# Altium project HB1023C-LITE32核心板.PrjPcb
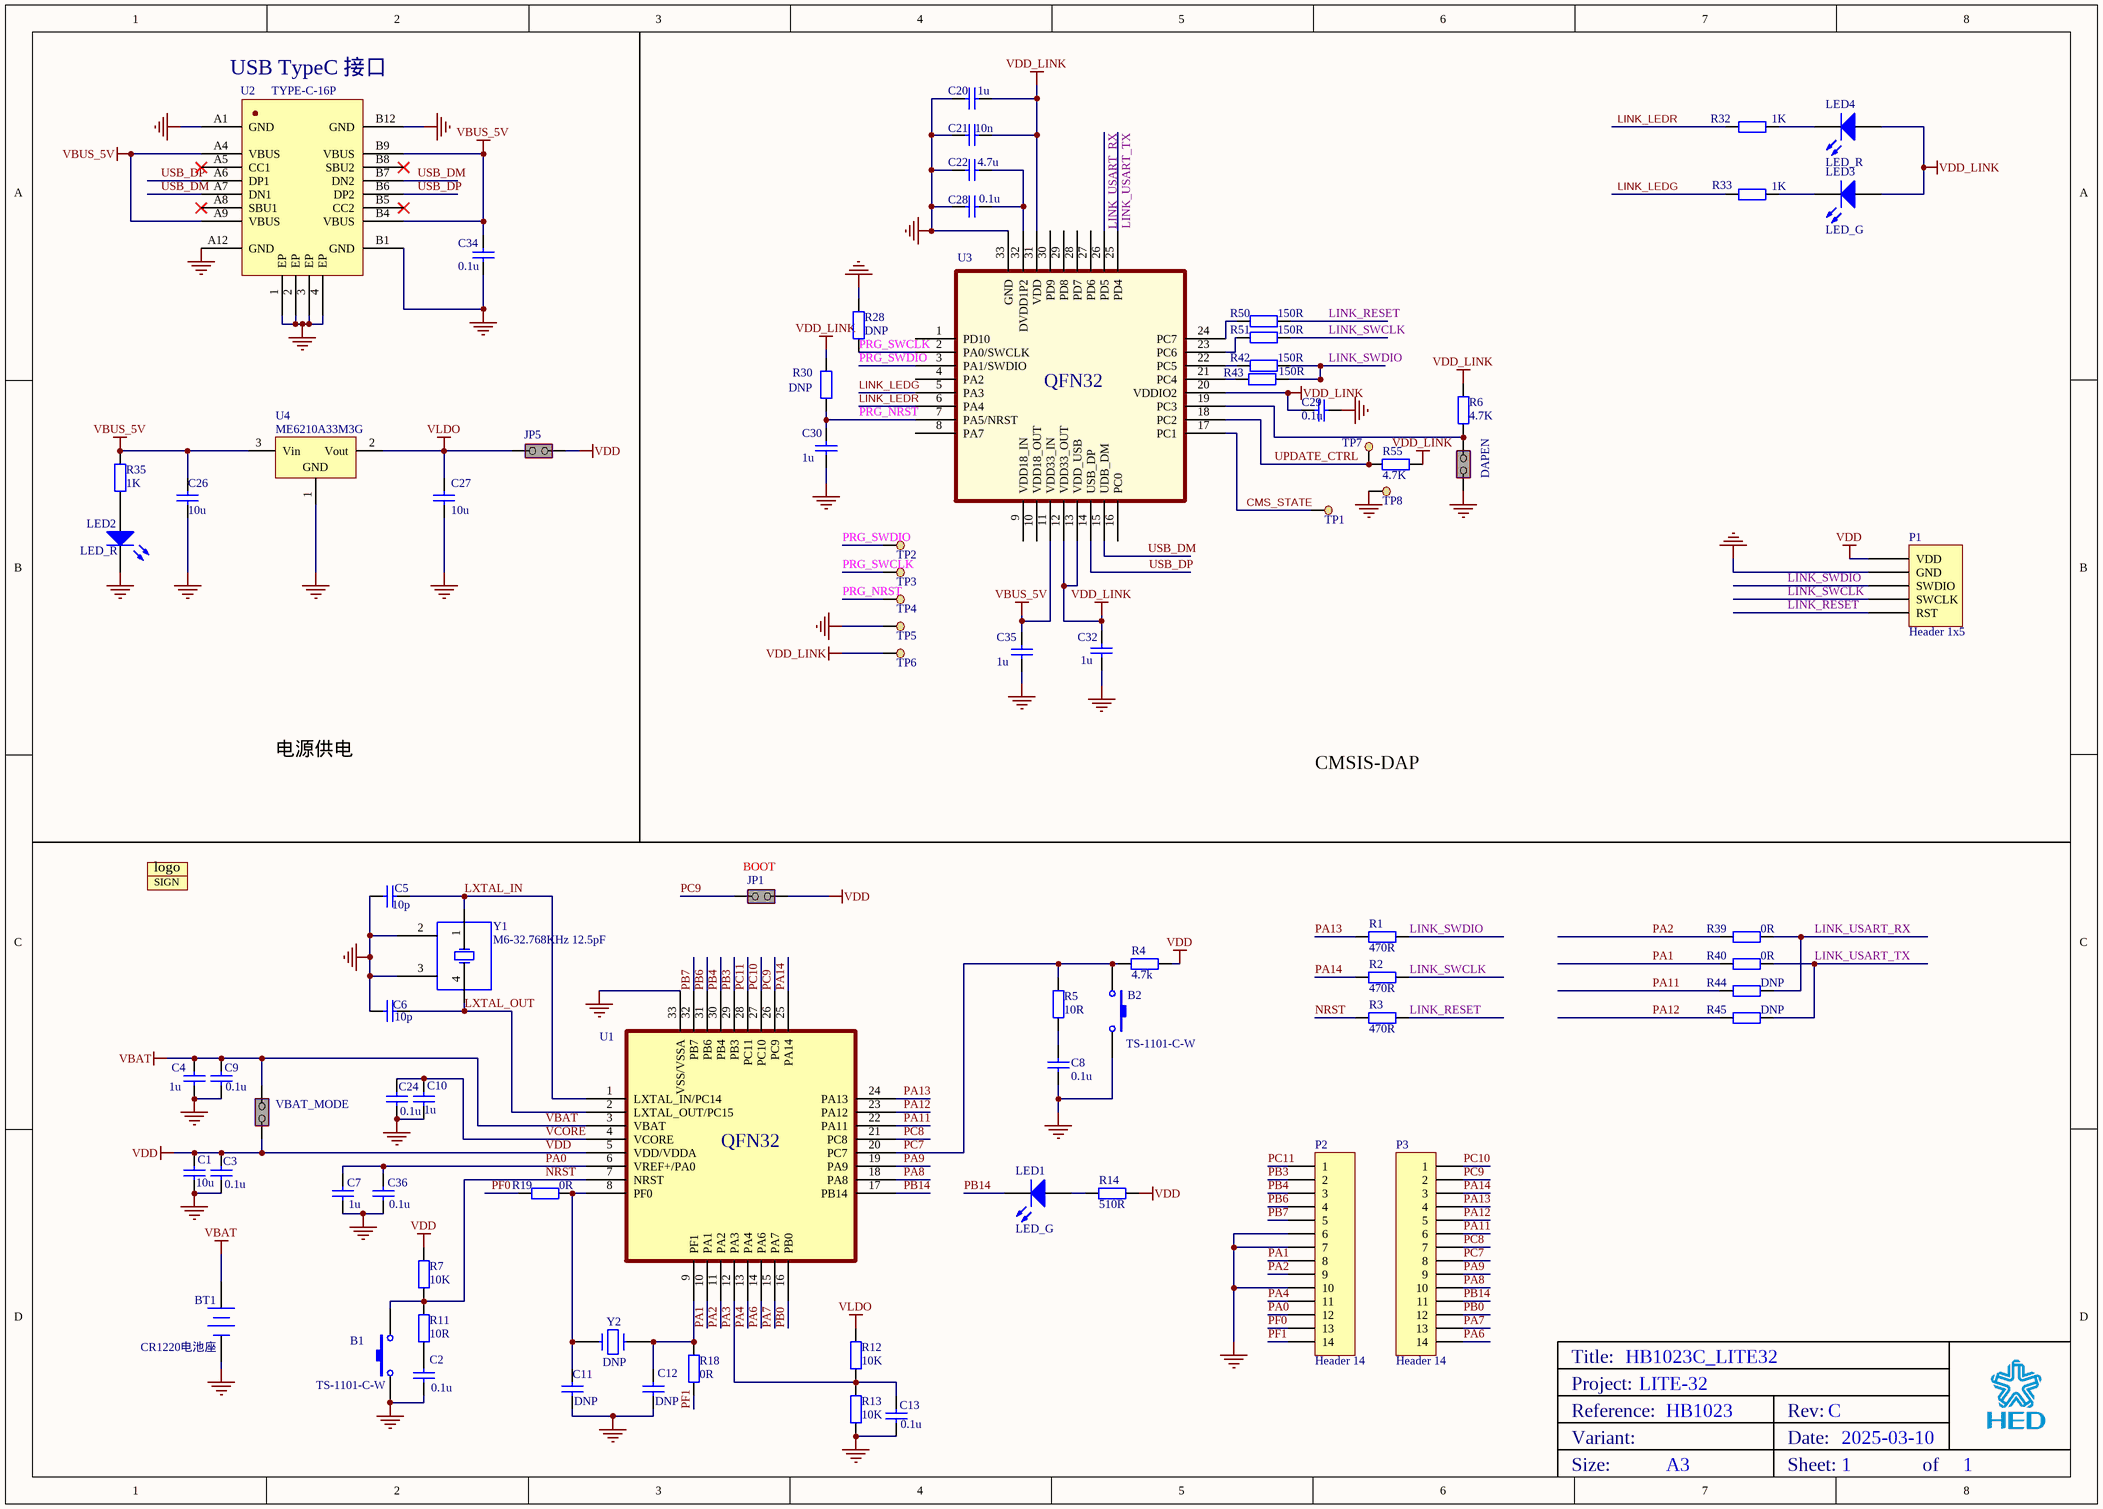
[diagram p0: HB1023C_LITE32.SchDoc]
Board_Reference: HB1023; Board_PCB_Revision: C; Board_Name: LITE-32; Board_Assembly_Revision: 01
1 sheet, 83 parts. Net scope: global (net labels, ports and power ports of the same name join across sheets).
Board file: HB1023C.PcbDoc

## Sheet HB1023C_LITE32.SchDoc: HB1023C_LITE32
size A3; Date: 2025-03-10; SheetNumber: 1; SheetTotal: 1

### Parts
B1  TS-1101-C-W  [按键_TS-1101-C-W]
B2  TS-1101-C-W  [按键_TS-1101-C-W]
BT1  CR1220电池座  [CR1220]
C1  10u  [0603]
C2  0.1u  [0603]
C3  0.1u  [0603]
C4  1u  [0603]
C5  10p  [0603]
C6  10p  [0603]
C7  1u  [0603]
C8  0.1u  [0603]
C9  0.1u  [0603]
C10  1u  [0603]
C11  DNP  [0603]
C12  DNP  [0603]
C13  0.1u  [0603]
C20  1u  [0603]
C21  10n  [0603]
C22  4.7u  [0603]
C24  0.1u  [0603]
C26  10u  [0603]
C27  10u  [0603]
C28  0.1u  [0603]
C29  0.1u  [0603]
C30  value 1u  [0603]  (hidden comment: 0.1u)
C32  1u  [0603]
C34  0.1u  [0603]
C35  1u  [0603]
C36  0.1u  [0603]
DAPEN  Header 1x2  [HEADER_1X2_2.54]  (value not drawn)
JP1  Header 1x2  [HEADER_1X2_2.54]  (value not drawn)
JP5  Header 1x2  [HEADER_1X2_2.54]  (value not drawn)
LED1  LED_G  [0603 - p]
LED2  LED_R  [0603-P]
LED3  LED_G  [0603-P]
LED4  LED_R  [0603-P]
logo1  logo  [LOGO]  (value not drawn)
logo2  SIGN  [SIGN]  (value not drawn)
P1  Header 1x5  [HDR1X5_2.54]
P2  Header 14  [HDR1X14]
P3  Header 14  [HDR1X14]
R1  470R  [0603]
R2  470R  [0603]
R3  470R  [0603]
R4  4.7k  [0603]
R5  10R  [0603]
R6  4.7K  [0603]
R7  10K  [0603]
R11  10R  [0603]
R12  10K  [0603]
R13  10K  [0603]
R14  510R  [0603]
R18  0R  [0603]
R19  0R  [0603]
R28  DNP  [0603]
R30  DNP  [0603]
R32  1K  [0603]
R33  1K  [0603]
R35  1K  [0603]
R39  0R  [0603]
R40  0R  [0603]
R42  150R  [0603]
R43  150R  [0603]
R44  DNP  [0603]
R45  DNP  [0603]
R50  150R  [0603]
R51  150R  [0603]
R55  4.7K  [0603]
TP1  TEST_POINT  [TEST_POINT]  (value not drawn)
TP2  TEST_POINT  [TEST_POINT]  (value not drawn)
TP3  TEST_POINT  [TEST_POINT]  (value not drawn)
TP4  TEST_POINT  [TEST_POINT]  (value not drawn)
TP5  TEST_POINT  [TEST_POINT]  (value not drawn)
TP6  TEST_POINT  [TEST_POINT]  (value not drawn)
TP7  TEST_POINT  [TEST_POINT]  (value not drawn)
TP8  TEST_POINT  [TEST_POINT]  (value not drawn)
U1  (no value)  [QFN_32N_4X4]
U2  TYPE-C-16P  [HED-KH-TYPE-C-16P]
U3  CIU98_H  [HED-QFN-32_5x5x05P]  (value not drawn)
U4  ME6210A33M3G  [SOT-23-3]
VBAT_MODE  Header 1x2  [HEADER_1X2_2.54]  (value not drawn)
Y1  M6-32.768KHz 12.5pF  [XTAL-MC146]
Y2  DNP  [XTAL_HC49/SMD]

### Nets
GND: B1.1 B2.1 BT1.2(-) C1.1 C2.2 C3.1 C4.1 C5.1 C6.1 C7.1 C8.1 C9.1 C10.2 C11.2 C12.2 C13.1 C20.1 C21.1 C22.1 C24.2 C26.1 C27.1 C28.1 C29.1 C30.2 C32.2 C34.1 C35.2 C36.1 DAPEN.2(NO) LED2.2(K) P1.2(GND) P2.6 P2.7 P2.10 R13.2 R28.1 TP5.1 TP8.1 U1.33(VSS/VSSA) U2.1(EP) U2.2(EP) U2.3(EP) U2.4(EP) U2.A1(GND) U2.A12(GND) U2.B1(GND) U2.B12(GND) U3.33(GND) U4.1(GND) Y1.2(OSC2) Y1.3(OSC4)
VBAT: BT1.1(+) C4.2 C9.2 U1.3(VBAT) VBAT_MODE.2(NO)
VBUS_5V: C26.2 C34.2 C35.1 R35.2 U2.A4(VBUS) U2.A9(VBUS) U2.B4(VBUS) U2.B9(VBUS) U3.11(VDD33_IN) U4.3(Vin)
VDD: C1.2 C3.2 JP1.2(NO) JP5.1(COMMON) P1.1(VDD) R4.2 R7.1 R14.2 U1.5(VDD/VDDA) VBAT_MODE.1(COMMON)
VDD_LINK: C20.2 C21.2 C29.2 C32.1 LED3.1(A) LED4.1(A) R6.2 R30.1 R55.1 TP6.1 U3.12(VDD33_OUT) U3.13(VDD_USB) U3.20(VDDIO2) U3.31(VDD)
VLDO: C27.2 JP5.2(NO) R12.2 U4.2(Vout)
CMS_STATE: TP1.1 U3.17(PC1)
LINK_LEDG: R33.1 U3.5(PA3)
LINK_LEDR: R32.1 U3.6(PA4)
LINK_RESET: P1.5(RST) R3.2 R50.2
LINK_SWCLK: P1.4(SWCLK) R2.2 R51.2
LINK_SWDIO: P1.3(SWDIO) R1.2 R42.2 R43.2
LINK_USART_RX: R39.1 R44.1 U3.26(PD5)
LINK_USART_TX: R40.1 R45.1 U3.25(PD4)
LXTAL_IN: C5.2 U1.1(LXTAL_IN/PC14) Y1.1(OSC1)
LXTAL_OUT: C6.2 U1.2(LXTAL_OUT/PC15) Y1.4(OSC3)
NRST: B1.2 R3.1 R7.2 R11.1 U1.7(NRST)
PA0: C7.2 C36.2 P2.12 U1.6(VREF+/PA0)
PA1: P2.8 R40.2 U1.10(PA1)
PA2: P2.9 R39.2 U1.11(PA2)
PA3: C13.2 R12.1 R13.1 U1.12(PA3)
PA4: P2.11 U1.13(PA4)
PA6: P3.14 U1.14(PA6)
PA7: P3.13 U1.15(PA7)
PA8: P3.10 U1.18(PA8)
PA9: P3.9 U1.19(PA9)
PA11: P3.6 R44.2 U1.22(PA11)
PA12: P3.5 R45.2 U1.23(PA12)
PA13: P3.4 R1.1 U1.24(PA13)
PA14: P3.3 R2.1 U1.25(PA14)
PB0: P3.12 U1.16(PB0)
PB3: P2.2 U1.29(PB3)
PB4: P2.3 U1.30(PB4)
PB6: P2.4 U1.31(PB6)
PB7: P2.5 U1.32(PB7)
PB14: LED1.2(K) P3.11 U1.17(PB14)
PC7: B2.2 P3.8 R4.1 R5.2 U1.20(PC7)
PC8: P3.7 U1.21(PC8)
PC9: JP1.1(COMMON) P3.2 U1.26(PC9)
PC10: P3.1 U1.27(PC10)
PC11: P2.1 U1.28(PC11)
PF0: P2.13 R19.2
PF1: P2.14 R18.2
PRG_NRST: C30.1 R30.2 TP4.1 U3.7(PA5/NRST)
PRG_SWCLK: R28.2 TP3.1 U3.2(PA0/SWCLK)
PRG_SWDIO: TP2.1 U3.3(PA1/SWDIO)
UPDATE_CTRL: R55.2 TP7.1 U3.18(PC2)
USB_DM: U2.A7(DN1) U2.B7(DN2) U3.15(UDB_DM)
USB_DP: U2.A6(DP1) U2.B6(DP2) U3.14(USB_DP)
VCORE: C10.1 C24.1 U1.4(VCORE)
NetC2_1: C2.1 R11.2
NetC8_2: C8.2 R5.1
NetC11_1: C11.1 R19.1 U1.8(PF0) Y2.1
NetC12_1: C12.1 R18.1 U1.9(PF1) Y2.2
NetC22_2: C22.2 C28.2 U3.32(DVDD1P2)
NetDAPEN_1: DAPEN.1(COMMON) R6.1 U3.19(PC3)
NetLED1_1: LED1.1(A) R14.1
NetLED2_1: LED2.1(A) R35.1
NetLED3_2: LED3.2(K) R33.2
NetLED4_2: LED4.2(K) R32.2
NetR42_1: R42.1 U3.22(PC5)
NetR43_1: R43.1 U3.21(PC4)
NetR50_1: R50.1 U3.24(PC7)
NetR51_1: R51.1 U3.23(PC6)

Not connected (* = marked no-connect by the designer): U2 A5(CC1)* A8(SBU1)* B5(CC2)* B8(SBU2)*; U3 1(PD10) 4(PA2) 8(PA7) 9(VDD18_IN) 10(VDD18_OUT) 16(PC0) 27(PD6) 28(PD7) 29(PD8) 30(PD9)

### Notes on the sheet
- (near U2) USB TypeC 接口
- 电源供电
- CMSIS-DAP
- (near JP1) BOOT
- Project:
- Title:
- Reference:
- Variant:
- Rev:
- Date:
- Size:
- A3
- Sheet:
- of

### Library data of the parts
B1 = SW-PB: Switch
B2 = SW-PB: 贴片按键
BT1 = Battery: Multicell Battery
C1 C9 C13 = MCD-00009: Capacitor, MLCC, 4.7uF, 16V, X5R, 10%, 0603, T=0.8mm; Manufacturer_Part_Number: CC0603KRX5R7BB475; Manufacturer: YAGEO; Provided_By: subcon; Initial_Board_Reference: mb1274
C2 C3 C7 C10 C20-C22 C24 C28-C30 C32 C35 C36 = MCD-00211: Capacitor, MLCC, 100nF, 16V, X7R, 10%, 0603, T=0,8mm; Manufacturer_Part_Number: CC0603KRX7R7BB104; Manufacturer: YAGEO; Provided_By: Subcon; Initial_Board_Reference: mb1319
C4 C26 C27 = MCD-00014: Capacitor, MLCC, 10uF, 25V, X5R, 10%, 0805, T=0,85mm; Manufacturer_Part_Number: CC0805KRX5R8BB106; Manufacturer: YAGEO; Provided_By: Subcon; Initial_Board_Reference: mb1274
C5 C6 = MCD-00666: Capacitor,5.6pF,0.1pF,16V,NPO,0603; Manufacturer_Part_Number: CC0603BRNPO7BN5R6; Manufacturer: YAGEO; Provided_By: Subcon; Initial_Board_Reference: MB1360
C8 = MCD-00211: 贴片电容; Manufacturer_Part_Number: CC0603KRX7R7BB104; Manufacturer: YAGEO; Provided_By: Subcon; Initial_Board_Reference: mb1319
C11 C12 = MCD-00009: 贴片电容33p; Manufacturer_Part_Number: CC0603KRX5R7BB475; Manufacturer: YAGEO; Provided_By: subcon; Initial_Board_Reference: mb1274
C34 = 0603 100nF 10% 50V: 贴片电容
DAPEN = MCD-00683: Header, 2x1, 2,54mm, VR, TH, Height 5.84mm/2.54mm; Part_Type: Connector; Manufacturer_Part_Number: TSW-102-07-x-S; Manufacturer: SAMTEC; Provided_By: Subcon; Initial_Board_Reference: MB1331
JP1 JP5 VBAT_MODE = MCD-00683: Header, 2x1, 2,54mm, VR, TH, Height 5.84mm/2.54mm - Shunt Fitted by default; Part_Type: Connector; Manufacturer_Part_Number: TSW-102-07-x-S; Manufacturer: SAMTEC; Provided_By: Subcon; Initial_Board_Reference: MB1331
LED1 LED3 = LED1: 贴片LED 绿色
LED2 LED4 = LED1: 贴片LED 红色
P1 = SWD: Header, 1x5, 2,54mm, VR, TH, Height 5.84mm/2.54mm
P2 P3 = Header 14: Header, 14-Pin
R1 = Res: 贴片电阻; Value: 51R
R2 R3 R28 R42 R43 R50 R51 = Res: 贴片电阻; Value: 1K
R4 R5 R11 R14 R18 R19 R30 = Res2: 贴片电阻; Value: 1K
R6 R55 = Res: 贴片电阻
R7 R12 R13 R32 R33 R35 R39 R40 R45 = Res2: 贴片电阻
R44 = Res2: 贴片电阻; Value: 0R
U1 = CIU32L051Kx-QFN32
U2 = KH-TYPE-C-16P: TYPE-C USB接口
U3 = CIU98-H: 贴片芯片
U4 = ME6210: 贴片LDO3.3V; Manufacturer: 微盟电子
Y1 = MC146: 贴片晶振
Y2 = XTAL_32K_NX3215SA: Crystal 32.768kHz, 6pF, -+20PPM, R=50K, SMD; Internal_Part_Number: MCD-00091; Part_Type: Crystal_Osc; Manufacturer_Part_Number: NX3215SA 32.768KHz EXS00A-MU00525; Manufacturer: NDK; ECCN_US: EAR99; ECCN_EU: NEC; Provided_By: STM; Initial_Board_Reference: mb1274

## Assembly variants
Default: all parts fitted
HB1023B01_BOM-L051: not fitted C11 C12 logo1 logo2 R28 R30 R44 R45 TP1 TP2 TP3 TP4 TP5 TP6 TP7 TP8 Y2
